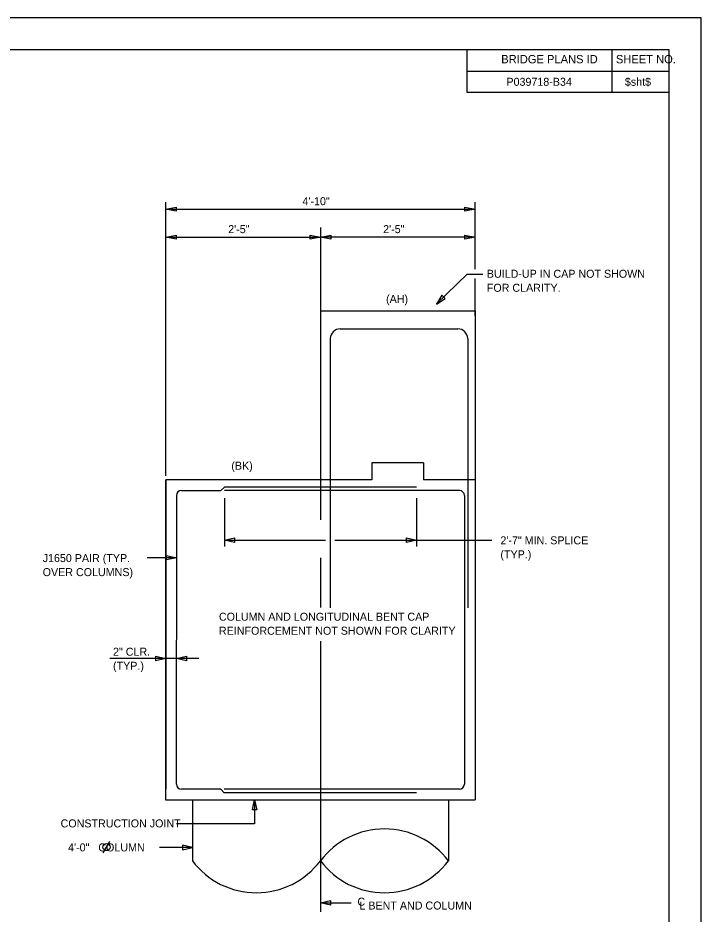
# Model space of a CAD drawing. Extents: x 1970675.2 to 1970711.3, y 796145.2 to 796167.2.
# Drawn here: x 1970700.57 to 1970711.24, y 796153.25 to 796167.25 of the extents above; entities that cross this region are included whole.
import ezdxf

# ---------------------------------------------------------------- set-up
doc = ezdxf.new("R2010")
doc.units = 0
for name, color, linetype in [('BR_AUTO DIMENSION', 7, 'Continuous'), ('BR_BORDER LINES', 7, 'Continuous'), ('BR_CENTER LINES', 7, 'Continuous'), ('BR_CONCRETE', 7, 'Continuous'), ('BR_REBAR', 7, 'Continuous'), ('BR_TEXT', 7, 'Continuous'), ('Level 31', 7, 'Continuous')]:
    doc.layers.add(name, color=color, linetype=linetype)

msp = doc.modelspace()

# ---------------------------------------------------------------- linework, layer by layer
at = {"layer": 'BR_AUTO DIMENSION'}
for p, q in [((1970702.874, 796160.092), (1970702.874, 796164.366)), ((1970707.707, 796163.323), (1970707.707, 796164.367)), ((1970702.874, 796164.259), (1970707.707, 796164.259)), ((1970702.874, 796163.822), (1970705.29, 796163.822)), ((1970707.707, 796163.822), (1970705.29, 796163.822)), ((1970707.707, 796162.592), (1970707.707, 796163.173)), ((1970703.79, 796159.742), (1970703.79, 796158.989)), ((1970706.79, 796159.742), (1970706.79, 796158.989)), ((1970703.79, 796159.086), (1970705.372, 796159.086)), ((1970705.515, 796159.086), (1970707.966, 796159.086)), ((1970703.04, 796158.814), (1970702.586, 796158.814)), ((1970703.391, 796157.237), (1970701.999, 796157.237)), ((1970704.263, 796155.029), (1970704.263, 796154.657)), ((1970704.263, 796154.657), (1970703.04, 796154.657)), ((1970703.29, 796154.288), (1970702.778, 796154.288)), ((1970705.29, 796153.422), (1970705.773, 796153.422))]:
    msp.add_line(p, q, dxfattribs=at)
for points in [[(1970703.036, 796164.227), (1970702.874, 796164.259), (1970703.036, 796164.29)], [(1970707.545, 796164.29), (1970707.707, 796164.259), (1970707.545, 796164.228)], [(1970703.036, 796163.791), (1970702.874, 796163.822), (1970703.036, 796163.853)], [(1970705.128, 796163.853), (1970705.29, 796163.822), (1970705.128, 796163.791)], [(1970705.453, 796163.791), (1970705.29, 796163.822), (1970705.453, 796163.853)], [(1970707.545, 796163.853), (1970707.707, 796163.822), (1970707.545, 796163.791)], [(1970707.186, 796162.915), (1970707.104, 796162.777), (1970707.238, 796162.865)], [(1970703.946, 796159.05), (1970703.79, 796159.086), (1970703.946, 796159.122)], [(1970706.634, 796159.122), (1970706.79, 796159.086), (1970706.634, 796159.05)], [(1970702.884, 796158.85), (1970703.04, 796158.814), (1970702.884, 796158.778)], [(1970702.717, 796157.273), (1970702.873, 796157.237), (1970702.717, 796157.201)], [(1970703.196, 796157.201), (1970703.04, 796157.237), (1970703.196, 796157.273)], [(1970704.227, 796154.873), (1970704.263, 796155.029), (1970704.299, 796154.873)], [(1970703.134, 796154.252), (1970703.29, 796154.288), (1970703.134, 796154.324)], [(1970705.446, 796153.386), (1970705.29, 796153.422), (1970705.446, 796153.458)]]:
    msp.add_lwpolyline(points, close=True, dxfattribs=at)
msp.add_lwpolyline([(1970707.104, 796162.778), (1970707.584, 796163.245), (1970707.828, 796163.245)], dxfattribs=at)
at = {"layer": 'BR_BORDER LINES'}
for p, q in [((1970710.736, 796166.746), (1970677.07, 796166.746)), ((1970707.584, 796166.08), (1970707.584, 796166.746)), ((1970709.85, 796166.08), (1970709.85, 796166.746)), ((1970710.736, 796145.746), (1970710.736, 796166.746)), ((1970707.584, 796166.417), (1970710.736, 796166.417)), ((1970709.85, 796166.417), (1970710.736, 796166.417)), ((1970710.736, 796166.08), (1970707.584, 796166.08))]:
    msp.add_line(p, q, dxfattribs=at)
at = {"layer": 'BR_CENTER LINES'}
for p, q in [((1970705.29, 796163.97), (1970705.29, 796162.529)), ((1970705.29, 796161.47), (1970705.29, 796159.406)), ((1970705.29, 796158.811), (1970705.29, 796158.033)), ((1970705.29, 796157.509), (1970705.29, 796153.282))]:
    msp.add_line(p, q, dxfattribs=at)
at = {"layer": 'BR_CONCRETE'}
for p, q in [((1970705.291, 796162.67), (1970705.291, 796160.029)), ((1970705.291, 796162.67), (1970707.707, 796162.67)), ((1970707.707, 796162.67), (1970707.707, 796160.029)), ((1970706.901, 796160.298), (1970706.096, 796160.298)), ((1970706.096, 796160.298), (1970706.096, 796160.029)), ((1970706.901, 796160.298), (1970706.901, 796160.029)), ((1970702.874, 796160.029), (1970702.874, 796155.196)), ((1970702.874, 796155.029), (1970702.874, 796160.029)), ((1970705.29, 796160.029), (1970702.874, 796160.029)), ((1970706.096, 796160.029), (1970705.29, 796160.029)), ((1970707.707, 796160.029), (1970706.901, 796160.029)), ((1970707.707, 796160.029), (1970707.707, 796155.029)), ((1970702.873, 796155.029), (1970703.29, 796155.029)), ((1970703.29, 796155.029), (1970707.29, 796155.029)), ((1970703.29, 796155.029), (1970703.29, 796154.078)), ((1970707.29, 796155.029), (1970707.706, 796155.029)), ((1970707.29, 796155.029), (1970707.29, 796154.078))]:
    msp.add_line(p, q, dxfattribs=at)
for centre, start, end in [((1970706.29, 796153.324), 37.0023, 142.9977), ((1970704.29, 796154.831), 217.0023, 322.9977), ((1970706.29, 796154.831), 217.0023, 322.9977)]:
    msp.add_arc(centre, 1.252, start, end, dxfattribs=at)
at = {"layer": 'BR_REBAR'}
for p, q in [((1970705.599, 796162.39), (1970707.437, 796162.39)), ((1970705.445, 796162.237), (1970705.445, 796158.029)), ((1970707.591, 796162.237), (1970707.591, 796158.029)), ((1970703.118, 796159.863), (1970703.735, 796159.863)), ((1970703.735, 796159.863), (1970703.79, 796159.918)), ((1970706.79, 796159.918), (1970703.79, 796159.918)), ((1970707.462, 796159.862), (1970703.79, 796159.863)), ((1970703.04, 796159.785), (1970703.039, 796155.275)), ((1970707.54, 796159.784), (1970707.54, 796155.524)), ((1970707.539, 796159.534), (1970707.539, 796155.274)), ((1970703.734, 796155.196), (1970703.118, 796155.197)), ((1970703.734, 796155.196), (1970703.789, 796155.141)), ((1970707.461, 796155.196), (1970703.789, 796155.196)), ((1970706.789, 796155.141), (1970703.789, 796155.141))]:
    msp.add_line(p, q, dxfattribs=at)
for centre, radius, start, end in [((1970705.601, 796162.234), 0.156, 91.025, 178.975), ((1970707.435, 796162.234), 0.156, 1.025, 88.975), ((1970703.118, 796159.785), 0.0781, 90, 180), ((1970707.462, 796159.784), 0.0781, 360, 90), ((1970703.118, 796155.275), 0.0781, 180, 270), ((1970707.461, 796155.274), 0.0781, 270, 360)]:
    msp.add_arc(centre, radius, start, end, dxfattribs=at)
at = {"layer": 'BR_TEXT'}
for p, q in [((1970703.79, 796159.086), (1970703.868, 796159.086)), ((1970701.896, 796154.201), (1970702.001, 796154.382))]:
    msp.add_line(p, q, dxfattribs=at)
msp.add_circle((1970701.949, 796154.292), 0.055, dxfattribs=at)
at = {"layer": 'Level 31'}
msp.add_line((1970711.236, 796167.246), (1970675.236, 796167.246), dxfattribs=at)
msp.add_lwpolyline([(1970675.236, 796167.246), (1970675.236, 796145.246), (1970711.236, 796145.246), (1970711.236, 796167.246)], dxfattribs=at)

# ---------------------------------------------------------------- texts
at = {"layer": 'BR_AUTO DIMENSION'}
for s, p in [('4\'-10"', (1970705.01, 796164.321)), ('2\'-5"', (1970703.85, 796163.884)), ('2\'-5"', (1970706.27, 796163.884)), ('(AH)', (1970706.316, 796162.794)), ('(BK)', (1970703.899, 796160.188))]:
    msp.add_text(s, height=0.125, dxfattribs=at).set_placement(p)
at = {"layer": 'BR_TEXT'}
for s, height, p in [('BRIDGE PLANS ID', 0.13, (1970708.115, 796166.537)), ('SHEET NO.', 0.13, (1970709.906, 796166.537)), ('P039718-B34', 0.125, (1970708.196, 796166.186)), ('$sht$', 0.125, (1970710.046, 796166.186))]:
    msp.add_text(s, height=height, dxfattribs=at).set_placement(p)
for s, p in [('BUILD-UP IN CAP NOT SHOWN', (1970707.89, 796163.187)), ('FOR CLARITY.', (1970707.89, 796162.968)), ('2\'-7" MIN. SPLICE', (1970708.102, 796159.022)), ('J1650 PAIR (TYP.', (1970700.952, 796158.745)), ('(TYP.)', (1970708.102, 796158.803)), ('OVER COLUMNS)', (1970700.952, 796158.526)), ('COLUMN AND LONGITUDINAL BENT CAP', (1970703.705, 796157.829)), ('REINFORCEMENT NOT SHOWN FOR CLARITY', (1970703.705, 796157.61)), ('2" CLR.', (1970702.051, 796157.282)), ('(TYP.)', (1970702.051, 796157.063)), ('CONSTRUCTION JOINT', (1970701.232, 796154.6)), ('4\'-0"   COLUMN', (1970701.349, 796154.225)), ('C', (1970705.869, 796153.377)), ('L BENT AND COLUMN', (1970705.9, 796153.317))]:
    msp.add_text(s, height=0.125, rotation=360, dxfattribs=at).set_placement(p)

doc.saveas('drawing.dxf')
